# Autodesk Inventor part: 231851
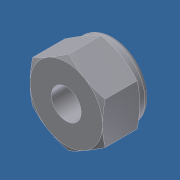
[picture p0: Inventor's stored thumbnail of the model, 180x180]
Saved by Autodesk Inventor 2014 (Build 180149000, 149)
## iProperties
Shininess: 20.0
Length Units: 11272
Angle Units: 11279
Time Units: 11290
Mass Units: 11286
Length Display Precision: 3
Angle Display Precision: 2
Company: Autodesk, Inc.
Created: 2001-10
Part Number: 231851
Material: Stainless Steel, 440C
Description: Nut, Esna; 3/8~16 (SS)
Document SubType Name: Modeling
Designer: Autodesk, Inc.
Density: 7.75 g/cm^3
Mass: 10.1235 g
Surface Area: 10.6126 cm^2
Volume: 1.30626 cm^3
Appearance: Steel
Density: 8.94
Volumn: 1.3062604850048036
Area: 10.612586411503024
PropertySet Name: Model Information
Control State: 0
Master: False
Checked Out: True
Last Check In By: JT
Last Check In Date: 2003-06-20
MODEL - 1: ---
MODEL - 2: ---
RAW MATERIAL: --------
SCALE:: 1=??
SIZE: 00 x 00 x 00
SUB-ASSY - 1: ------
SUB-ASSY - 1 - QUA: 1
SUB-ASSY - 2: ------
SUB-ASSY - 2 - QUA: 1
SYM. TO:: N/A
TEMPLATE CREATION: -- / __-__-__
Author: Autodesk, Inc.
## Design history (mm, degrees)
derived "Lock-nut.ipt"
body "Solid1"
tag "TaggingFeature2"
feature "Solid1::Lock-nut.ipt" dims "ScaleForDerivedMember" = 10
